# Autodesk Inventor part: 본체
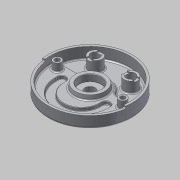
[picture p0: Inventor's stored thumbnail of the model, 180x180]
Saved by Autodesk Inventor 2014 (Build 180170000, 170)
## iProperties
Created: 2015-06
Part Number: 본체
Material: 알루미늄 6061
Document SubType Name: Modeling
Designer: MYHOME
Mass: 1071 g
Surface Area: 1034.49 cm^2
Volume: 395.202 cm^3
Density: 2.71 g/cm^3
Appearance: 알루미늄 - 평지
Author: MYHOME
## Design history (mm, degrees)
sketch "스케치7"
  geometry: C1 r 95 at (0, 0); 1 further point
  constraints: 1 centre point, 1 coincident
  dimensions: "d19" = 190 diameter of C1
extrude "돌출6" new body sketch "스케치7" distance "d20" = 32; taper "d21" = 0 deg
sketch "스케치8"
  geometry: C1 r 95 at (0, 0) reference; C2 r 90 at (0, 0)
  constraints: 1 centre point, 1 coincident
  dimensions: "d22" = 180 diameter of C2
extrude "돌출7" cut sketch "스케치8" distance "d23" = 18; taper "d24" = 0 deg
sketch "스케치9"
  geometry: L1 (38.833, 16)-(88.566, 16); L2 (-38.833, 16)-(-88.566, 16); A1 r 90 centre (0, 0) between (88.566, 16) and (-88.566, 16) reference; A2 r 42 centre (0, 0) between (38.833, 16) and (-38.833, 16)
  constraints: 4 end point, 4 point on circle, 1 centre point, 1 coincident, 1 collinear, 1 horizontal
  dimensions: "d25" = 42 radius of A2; "d26" = 16 distance from line of A1.centre L1; "d27" = 16 distance from line of A1.centre L2
extrude "돌출8" cut sketch "스케치9" distance "d28" = 7; taper "d29" = 0 deg
sketch "스케치10"
  geometry: C1 r 95 at (0, 0) reference; C2 r 26 at (0, 0)
  constraints: 1 centre point, 1 coincident
  dimensions: "d30" = 52 diameter of C2
extrude "돌출9" join sketch "스케치10" distance "d31" = 12; taper "d32" = -15 deg
sketch "스케치11"
  geometry: C1 r 22.785 at (0, 0) reference; C2 r 11.5 at (0, 0)
  constraints: 1 centre point, 1 coincident
  dimensions: "d33" = 23 diameter of C2
sketch "스케치12"
  geometry: C1 r 35 at (0, 0); A1 r 90 centre (0, 0) between (-88.566, 16) and (88.566, 16) reference
  constraints: 1 centre point, 1 coincident
  dimensions: "d34" = 70 diameter of C1
extrude "돌출10" join sketch "스케치12" distance "d35" = 10; taper "d36" = -10 deg
sketch "스케치13"
  geometry: C1 r 33.237 at (0, 0) reference; C2 r 25 at (0, 0)
  constraints: 1 centre point, 1 coincident
  dimensions: "d37" = 50 diameter of C2
extrude "돌출11" cut sketch "스케치13" distance "d38" = 15; taper "d39" = 0 deg
extrude "돌출12" cut sketch "스케치11" stored distance "d40" = 15; taper "d41" = 0 deg
sketch "스케치17"
  geometry: C1 r 15 at (-40, 52); C2 r 15 at (40, 52); A1 r 90 centre (0, 0) between (88.566, 16) and (-88.566, 16) reference
  constraints: 2 centre point
  dimensions: "d54" = 30 diameter of C1; "d55" = 30 diameter of C2; "d56" = 80 distance of C1.centre C2.centre; "d57" = 52 vertical distance of C2.centre A1.centre; "d59" = 52 vertical distance of A1.centre C1.centre; "d60" = 40 horizontal distance of A1.centre C2.centre
extrude "돌출16" join sketch "스케치17" distance "d61" = 25; taper "d62" = 0 deg
sketch "스케치18"
  geometry: L1 (-6, 17.367)-(6, 17.367); L2 (6, 17.367)-(6, -23.372); L3 (6, -23.372)-(-6, -23.372); L4 (-6, -23.372)-(-6, 17.367); C1 r 15 at (0, 0) reference; C2 r 15 at (80, 0) reference; 2 further points
  constraints: 8 end point, 2 parallel, 1 horizontal, 1 midpoint, 1 perpendicular, 1 vertical alignment
  dimensions: "d63" = 12 distance of L1.start L1.end
extrude "돌출17" cut sketch "스케치18" distance "d64" = 3; taper "d65" = 0 deg
sketch "스케치19"
  geometry: L1 (-19.836, 6)-(21.404, 6); L2 (21.404, 6)-(21.404, -6); L3 (21.404, -6)-(-19.836, -6); L4 (-19.836, -6)-(-19.836, 6); C1 r 15 at (0, 0) reference; 2 further points
  constraints: 8 end point, 2 parallel, 1 horizontal, 1 horizontal alignment, 1 midpoint, 1 perpendicular
  dimensions: "d66" = 12 distance of L1.end L2.end
extrude "돌출18" cut sketch "스케치19" distance "d67" = 3; taper "d68" = 0 deg
sketch "스케치20"
  geometry: L1 (-34, 65.748)-(-34, 38.252) reference; L2 (-46, 38.252)-(-46, 65.748) reference; L3 (-34, 65.748)-(-34, 38.252) reference; L4 (-46, 38.252)-(-46, 65.748) reference; L5 (53.748, 46)-(26.252, 46) reference; L6 (26.252, 58)-(53.748, 58) reference; L7 (53.748, 46)-(26.252, 46) reference; L8 (26.252, 58)-(53.748, 58) reference; C1 r 10 at (-40, 52); C2 r 10 at (40, 52); A1 r 15 centre (-40, 52) between (-34, 38.252) and (-34, 65.748) reference; A2 r 15 centre (-40, 52) between (-46, 65.748) and (-46, 38.252) reference; A3 r 15 centre (-40, 52) between (-46, 38.252) and (-34, 38.252) reference; A4 r 15 centre (-40, 52) between (-34, 65.748) and (-46, 65.748) reference; A5 r 15 centre (40, 52) between (26.252, 58) and (26.252, 46) reference; A6 r 15 centre (40, 52) between (53.748, 46) and (53.748, 58) reference; A7 r 15 centre (40, 52) between (26.252, 46) and (53.748, 46) reference; A8 r 15 centre (40, 52) between (53.748, 58) and (26.252, 58) reference
  constraints: 2 centre point, 2 coincident
  dimensions: "d69" = 20 diameter of C1; "d70" = 20 diameter of C2
extrude "돌출19" cut sketch "스케치20" stored distance "d71" = 3; taper "d72" = 0 deg
sketch "스케치21"
  geometry: L1 (-38.833, 16)-(-88.566, 16) reference; L2 (59, -19)-(59, -14); L3 (41, -19)-(41, -14); L4 (-41, -19)-(-41, -14); L5 (-59, -19)-(-59, -14); L6 (-59, -14)-(-41, -14); L7 (41, -14)-(59, -14); C1 r 35 at (0, 0) reference; A1 r 41 centre (0, -19) between (-41, -19) and (41, -19); A2 r 59 centre (0, -19) between (-59, -19) and (59, -19); A3 r 9 centre (-50, -14) between (-41, -14) and (-59, -14); A4 r 9 centre (50, -14) between (59, -14) and (41, -14)
  constraints: 12 end point, 8 point on circle, 4 centre point, 4 equal length, 4 horizontal alignment, 4 tangent, 2 midpoint, 2 perpendicular, 1 coincident, 1 vertical alignment
  dimensions: "d73" = 19 distance of A1.centre C1.centre; "d74" = 41 radius of A1; "d75" = 59 radius of A2; "d80" = 5 distance of L2.start L2.end; "d81" = 5 distance of L5.start L5.end
extrude "돌출20" cut sketch "스케치21" distance "d82" = 7; taper "d83" = 0 deg
sketch "스케치22"
  geometry: L1 (0, 0)-(94.075, -13.221); L2 (0, 0)-(110.218, 0); L3 (0, 0)-(-94.075, -13.221); L4 (0, 0)-(114.278, 0); A1 r 95 centre (0, 0) between (94.075, -13.221) and (-94.075, -13.221) reference; A2 r 90 centre (0, 0) between (-89.124, -12.526) and (89.124, -12.526); A3 r 95 centre (0, 0) between (-94.075, -13.221) and (94.075, -13.221); 1 further point
  constraints: 8 end point, 6 point on circle, 2 centre point, 2 coincident, 2 horizontal, 1 point on line, 2 other
  dimensions: "d84" = 8 deg angle of L1 L2; "d85" = 172 deg angle of L3 L4
extrude "돌출21" cut sketch "스케치22" distance "d86" = 5; taper "d87" = 0 deg
fillet "모깎기1" dims "d88" = 10
fillet "모깎기3" dims "d90" = 3
fillet "모깎기4" dims "d91" = 10
fillet "모깎기5" dims "d92" = 3
fillet "모깎기6" dims "d93" = 3
fillet "모깎기7" dims "d97" = 3
chamfer "모따기2" distance "d98" = 1; stored, may be unused: second distance "d99" = 2, angle "d100" = 45 deg
fillet "모깎기8" dims "d101" = 5
fillet "모깎기9" dims "d105" = 3
sketch "스케치23"
  geometry: C1 r 90 at (0, 0) reference; C2 r 68 at (0, 0)
  constraints: 1 centre point, 1 coincident, 1 other
  dimensions: "d107" = 136 diameter of C2
feature "엠보싱1" sketch "스케치23" dims "d19" = 190, "d108" = 0.5, "d109" = 0
chamfer "모따기4" distance "d110" = 1; stored, may be unused: second distance "d111" = 2, angle "d112" = 45 deg
fillet "모깎기10" dims "d113" = 0.3
sketch "스케치24"
  geometry: C1 r 90 at (0, 0) reference; C2 r 28.302 at (0, 0) reference; C3 r 9 at (74, 0); C4 r 9 at (-74, 0); A1 r 74 centre (0, 0) between (74, 0) and (-74, 0)
  constraints: 3 centre point, 2 horizontal alignment, 2 point on circle, 1 coincident
  dimensions: "d114" = 148 diameter of A1; "d115" = 18 diameter of C3; "d116" = 18 diameter of C4
extrude "돌출22" cut sketch "스케치24" distance "d117" = 11; taper "d118" = 0 deg
sketch "스케치25"
  geometry: C1 r 9 at (0, 0) reference; C2 r 9 at (148, 0) reference; C3 r 5.5 at (0, 0); C4 r 5.5 at (148, 0); 1 further point
  constraints: 2 centre point, 2 coincident
  dimensions: "d119" = 11 diameter of C3; "d120" = 11 diameter of C4
extrude "돌출23" cut sketch "스케치25" stored distance "d121" = 11; taper "d122" = 0 deg
sketch "스케치26"
  geometry: C1 r 5.5 at (74, 0) reference; C2 r 5.5 at (-74, 0) reference; C3 r 9 at (-74, 0); C4 r 9 at (74, 0)
  constraints: 2 centre point, 2 coincident
  dimensions: "d123" = 18 diameter of C3; "d124" = 18 diameter of C4
extrude "돌출24" join sketch "스케치26" distance "d125" = 18; taper "d126" = 0 deg
fillet "모깎기11" dims "d127" = 3
fillet "모깎기12" dims "d128" = 1
chamfer "모따기5" distance "d129" = 1; stored, may be unused: second distance "d130" = 2, angle "d131" = 45 deg
node "솔리드2"
node "투영된 루프2"
node "투영된 루프3"
node "투영된 루프4"
node "투영된 루프5"
node "투영된 루프6"
node "투영된 루프7"
node "투영된 루프8"
node "투영된 루프9"
other parameters: "d79" = 5
